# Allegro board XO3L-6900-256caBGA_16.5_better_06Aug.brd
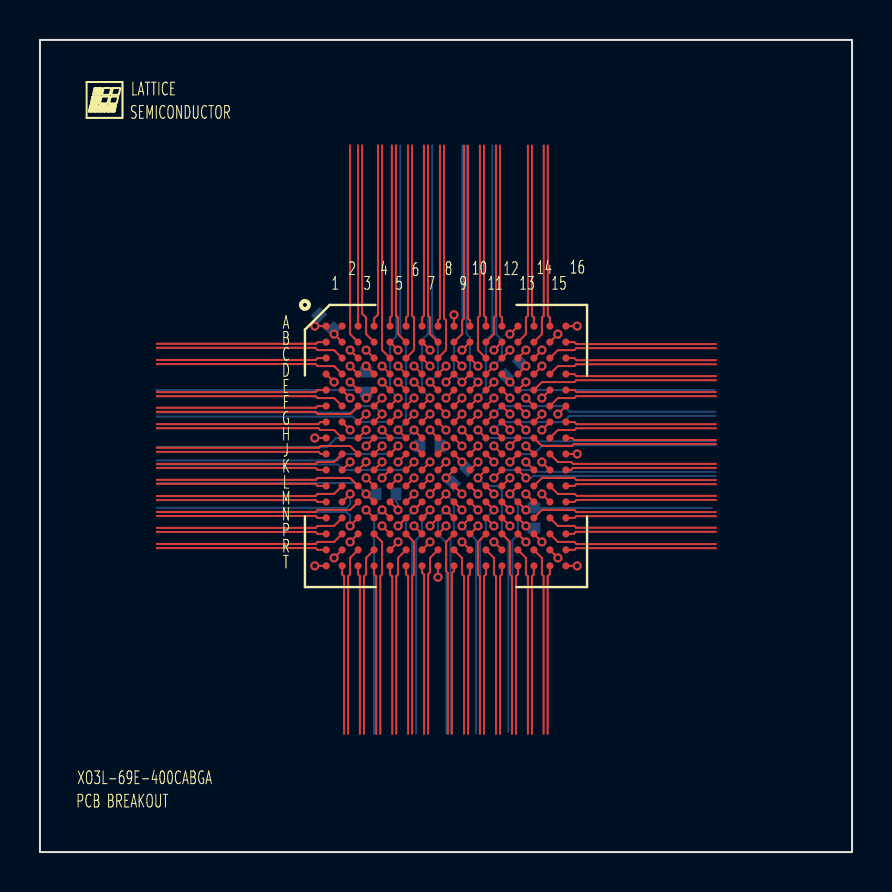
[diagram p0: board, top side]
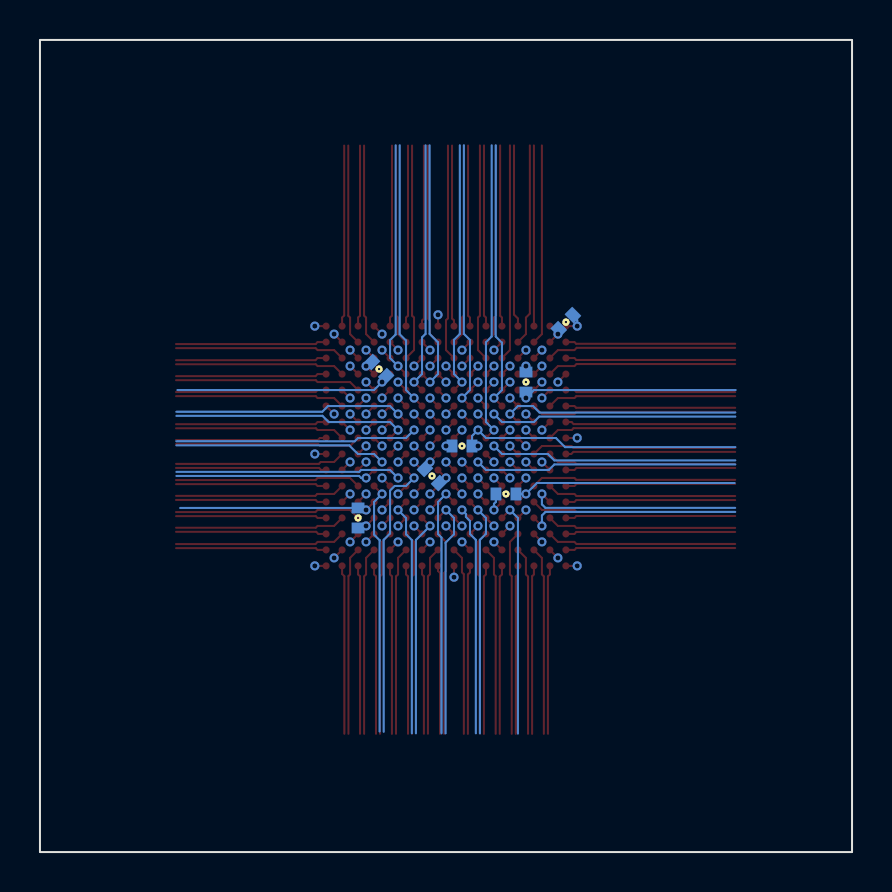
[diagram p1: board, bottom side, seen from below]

Outline 40.64 x 40.64 mm; copper layers: TOP, L2_GND, L3_SIGNAL, L4_SIGNAL, L5_PWR, BOTTOM. Coordinates in mm from the lower left corner of the outline.
Outline path: rectangle 0,0 40.64,40.64

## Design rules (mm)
net group CDPB4: nets PB4C PB4D
net group CDPB13: nets PB13C PB13D
net group CDPB18: nets PB18C PB18D
net group CDPB26: nets PB26C PB26D
net group CDPB31: nets PB31C PB31D
net group CDPB38: nets PB38C PB38D
net group CDPL2: nets PL2C PL2D
net group CDPL4: nets PL4C PL4D
net group CDPL6: nets PL6C PL6D
net group CDPL7: nets PL7C PL7D
net group CDPL9: nets PL9C PL9D
net group CDPL10: nets PL10C PL10D
net group CDPL15: nets PL15C PL15D
net group CDPL16: nets PL16C PL16D
net group CDPL19: nets PL19C PL19D
net group CDPL21: nets PL21C PL21D
net group CDPL23: nets PL23C PL23D
net group CDPL25: nets PL25C PL25D
net group CDPR2: nets PR2C PR2D
net group CDPR4: nets PR4C PR4D
net group CDPR6: nets PR6C PR6D
net group CDPR7: nets PR7C PR7D
net group CDPR10: nets PR10C PR10D
net group CDPR11: nets PR11C PR11D
net group CDPR16: nets PR16C PR16D
net group CDPR17: nets PR17C PR17D
net group CDPR19: nets PR19C PR19D
net group CDPR21: nets PR21C PR21D
net group CDPR23: nets PR23C PR23D
net group CDPR25: nets PR25C PR25D
net group CDPT14: nets PT14C PT14D
net group CDPT17: nets PT17C PT17D
net group CDPT22: nets PT22C PT22D
net group CDPT27: nets PT27C PT27D
net group CDPT36: nets PT36C PT36D
net group PB4: nets PB4A PB4B
net group PB6: nets PB6A PB6B
net group PB7: nets PB7A PB7B
net group PB9: nets PB9A PB9B
net group PB10: nets PB10A PB10B
net group PB12: nets PB12A PB12B
net group PB13: nets PB13A PB13B
net group PB15: nets PB15A PB15B
net group PB16: nets PB16A PB16B
net group PB18: nets PB18A PB18B
net group PB21: nets PB21A PB21B
net group PB23: nets PB23A PB23B
net group PB26: nets PB26A PB26B
net group PB28: nets PB28A PB28B
net group PB29: nets PB29A PB29B
net group PB31: nets PB31A PB31B
net group PB34: nets PB34A PB34B
net group PB35: nets PB35A PB35B
net group PB37: nets PB37A PB37B
net group PB38: nets PB38A PB38B
net group PL3: nets PL3A PL3B
net group PL4: nets PL4A PL4B
net group PL6: nets PL6A PL6B
net group PL8: nets PL8A PL8B
net group PL9: nets PL9A PL9B
net group PL10: nets PL10A PL10B
net group PL11: nets PL11A PL11B
net group PL12: nets PL12A PL12B
net group PL15: nets PL15A PL15B
net group PL17: nets PL17A PL17B
net group PL19: nets PL19A PL19B
net group PL22: nets PL22A PL22B
net group PL24: nets PL24A PL24B
net group PL25: nets PL25A PL25B
net group PR2: nets PR2A PR2B
net group PR3: nets PR3A PR3B
net group PR5: nets PR5A PR5B
net group PR7: nets PR7A PR7B
net group PR9: nets PR9A PR9B
net group PR11: nets PR11A PR11B
net group PR12: nets PR12A PR12B
net group PR15: nets PR15A PR15B
net group PR16: nets PR16A PR16B
net group PR17: nets PR17A PR17B
net group PR18: nets PR18A PR18B
net group PR21: nets PR21A PR21B
net group PR23: nets PR23A PR23B
net group PR24: nets PR24A PR24B
net group PT9: nets PT9A PT9B
net group PT10: nets PT10A PT10B
net group PT11: nets PT11A PT11B
net group PT12: nets PT12A PT12B
net group PT14: nets PT14A PT14B
net group PT15: nets PT15A PT15B
net group PT16: nets PT16A PT16B
net group PT17: nets PT17A PT17B
net group PT18: nets PT18A PT18B
net group PT21: nets PT21A PT21B
net group PT22: nets PT22A PT22B
net group PT25: nets PT25A PT25B
net group PT26: nets PT26A PT26B
net group PT27: nets PT27A PT27B
net group PT28: nets PT28A PT28B
net group PT32: nets PT32A PT32B
net group PT33: nets PT33A PT33B
net group PT34: nets PT34A PT34B
net group PT35: nets PT35A PT35B
net group PT36: nets PT36A PT36B

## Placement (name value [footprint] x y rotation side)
BGA  -  [BGA256C80P16X16_1400X1400X17-1]  20.32 20.32 270 top
C1  VAL  [C0402]  16.32 23.52 90 bottom
C2  VAL  [C0402]  23.67 24.17 45 bottom
C3  VAL  [C0402]  14.32 26.52 315 bottom
C4  VAL  [C0402]  19.52 20.32 0 bottom
C5  VAL  [C0402]  24.72 16.72 270 bottom
C6  VAL  [C0402]  21.02 18.82 45 bottom
C7  VAL  [C0402]  17.32 17.92 0 bottom
NOREF  -  []  24.69 13 0 top

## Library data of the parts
BGA = BGA256C80P16X16_1400X1400X17-1
C1-C7 = C0402: User Part Number: UPN; Tolerance: TOL

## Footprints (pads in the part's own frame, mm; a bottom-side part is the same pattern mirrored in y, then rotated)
BGA256C80P16X16_1400X1400X17-1
  round 0.356 smd: A1(-6,-6) A2(-6,-5.2) A3(-6,-4.4) A4(-6,-3.6) A5(-6,-2.8) A6(-6,-2) A7(-6,-1.2) A8(-6,-0.4) A9(-6,0.4) A10(-6,1.2) A11(-6,2) A12(-6,2.8) A13(-6,3.6) A14(-6,4.4) A15(-6,5.2) A16(-6,6) B1(-5.2,-6) B2(-5.2,-5.2) B3(-5.2,-4.4) B4(-5.2,-3.6) B5(-5.2,-2.8) B6(-5.2,-2) B7(-5.2,-1.2) B8(-5.2,-0.4) B9(-5.2,0.4) B10(-5.2,1.2) B11(-5.2,2) B12(-5.2,2.8) B13(-5.2,3.6) B14(-5.2,4.4) B15(-5.2,5.2) B16(-5.2,6) C1(-4.4,-6) C2(-4.4,-5.2) C3(-4.4,-4.4) C4(-4.4,-3.6) C5(-4.4,-2.8) C6(-4.4,-2) C7(-4.4,-1.2) C8(-4.4,-0.4) C9(-4.4,0.4) C10(-4.4,1.2) C11(-4.4,2) C12(-4.4,2.8) C13(-4.4,3.6) C14(-4.4,4.4) C15(-4.4,5.2) C16(-4.4,6) D1(-3.6,-6) D2(-3.6,-5.2) D3(-3.6,-4.4) D4(-3.6,-3.6) D5(-3.6,-2.8) D6(-3.6,-2) D7(-3.6,-1.2) D8(-3.6,-0.4) D9(-3.6,0.4) D10(-3.6,1.2) D11(-3.6,2) D12(-3.6,2.8) D13(-3.6,3.6) D14(-3.6,4.4) D15(-3.6,5.2) D16(-3.6,6) E1(-2.8,-6) E2(-2.8,-5.2) E3(-2.8,-4.4) E4(-2.8,-3.6) E5(-2.8,-2.8) E6(-2.8,-2) E7(-2.8,-1.2) E8(-2.8,-0.4) E9(-2.8,0.4) E10(-2.8,1.2) E11(-2.8,2) E12(-2.8,2.8) E13(-2.8,3.6) E14(-2.8,4.4) E15(-2.8,5.2) E16(-2.8,6) F1(-2,-6) F2(-2,-5.2) F3(-2,-4.4) F4(-2,-3.6) F5(-2,-2.8) F6(-2,-2) F7(-2,-1.2) F8(-2,-0.4) F9(-2,0.4) F10(-2,1.2) F11(-2,2) F12(-2,2.8) F13(-2,3.6) F14(-2,4.4) F15(-2,5.2) F16(-2,6) G1(-1.2,-6) G2(-1.2,-5.2) G3(-1.2,-4.4) G4(-1.2,-3.6) G5(-1.2,-2.8) G6(-1.2,-2) G7(-1.2,-1.2) G8(-1.2,-0.4) G9(-1.2,0.4) G10(-1.2,1.2) G11(-1.2,2) G12(-1.2,2.8) G13(-1.2,3.6) G14(-1.2,4.4) G15(-1.2,5.2) G16(-1.2,6) H1(-0.4,-6) H2(-0.4,-5.2) H3(-0.4,-4.4) H4(-0.4,-3.6) H5(-0.4,-2.8) H6(-0.4,-2) H7(-0.4,-1.2) H8(-0.4,-0.4) H9(-0.4,0.4) H10(-0.4,1.2) H11(-0.4,2) H12(-0.4,2.8) H13(-0.4,3.6) H14(-0.4,4.4) H15(-0.4,5.2) H16(-0.4,6) J1(0.4,-6) J2(0.4,-5.2) J3(0.4,-4.4) J4(0.4,-3.6) J5(0.4,-2.8) J6(0.4,-2) J7(0.4,-1.2) J8(0.4,-0.4) J9(0.4,0.4) J10(0.4,1.2) J11(0.4,2) J12(0.4,2.8) J13(0.4,3.6) J14(0.4,4.4) J15(0.4,5.2) J16(0.4,6) K1(1.2,-6) K2(1.2,-5.2) K3(1.2,-4.4) K4(1.2,-3.6) K5(1.2,-2.8) K6(1.2,-2) K7(1.2,-1.2) K8(1.2,-0.4) K9(1.2,0.4) K10(1.2,1.2) K11(1.2,2) K12(1.2,2.8) K13(1.2,3.6) K14(1.2,4.4) K15(1.2,5.2) K16(1.2,6) L1(2,-6) L2(2,-5.2) L3(2,-4.4) L4(2,-3.6) L5(2,-2.8) L6(2,-2) L7(2,-1.2) L8(2,-0.4) L9(2,0.4) L10(2,1.2) L11(2,2) L12(2,2.8) L13(2,3.6) L14(2,4.4) L15(2,5.2) L16(2,6) M1(2.8,-6) M2(2.8,-5.2) M3(2.8,-4.4) M4(2.8,-3.6) M5(2.8,-2.8) M6(2.8,-2) M7(2.8,-1.2) M8(2.8,-0.4) M9(2.8,0.4) M10(2.8,1.2) M11(2.8,2) M12(2.8,2.8) M13(2.8,3.6) M14(2.8,4.4) M15(2.8,5.2) M16(2.8,6) N1(3.6,-6) N2(3.6,-5.2) N3(3.6,-4.4) N4(3.6,-3.6) N5(3.6,-2.8) N6(3.6,-2) N7(3.6,-1.2) N8(3.6,-0.4) N9(3.6,0.4) N10(3.6,1.2) N11(3.6,2) N12(3.6,2.8) N13(3.6,3.6) N14(3.6,4.4) N15(3.6,5.2) N16(3.6,6) P1(4.4,-6) P2(4.4,-5.2) P3(4.4,-4.4) P4(4.4,-3.6) P5(4.4,-2.8) P6(4.4,-2) P7(4.4,-1.2) P8(4.4,-0.4) P9(4.4,0.4) P10(4.4,1.2) P11(4.4,2) P12(4.4,2.8) P13(4.4,3.6) P14(4.4,4.4) P15(4.4,5.2) P16(4.4,6) R1(5.2,-6) R2(5.2,-5.2) R3(5.2,-4.4) R4(5.2,-3.6) R5(5.2,-2.8) R6(5.2,-2) R7(5.2,-1.2) R8(5.2,-0.4) R9(5.2,0.4) R10(5.2,1.2) R11(5.2,2) R12(5.2,2.8) R13(5.2,3.6) R14(5.2,4.4) R15(5.2,5.2) R16(5.2,6) T1(6,-6) T2(6,-5.2) T3(6,-4.4) T4(6,-3.6) T5(6,-2.8) T6(6,-2) T7(6,-1.2) T8(6,-0.4) T9(6,0.4) T10(6,1.2) T11(6,2) T12(6,2.8) T13(6,3.6) T14(6,4.4) T15(6,5.2) T16(6,6)
C0402
  rect 0.54x0.64 smd: 1(-0.5,0) 2(0.5,0)

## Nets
GND: BGA.B2 BGA.B15 BGA.C3 BGA.C14 BGA.D4 BGA.D13 BGA.E5 BGA.E12 BGA.F6 BGA.F11 BGA.H8 BGA.H9 BGA.J8 BGA.J9 BGA.L6 BGA.L11 BGA.M5 BGA.M12 BGA.N4 BGA.N13 BGA.P3 BGA.P14 BGA.R2 BGA.R15 C1.2 C2.2 C3.2 C4.2 C5.2 C6.2 C7.2
VCC: BGA.A1 BGA.A16 BGA.G7 BGA.G10 BGA.K7 BGA.K10 BGA.T1 BGA.T16 C3.1
VCCIO0: BGA.D5 BGA.D12 BGA.G8 BGA.G9 C2.1
VCCIO1: BGA.E13 BGA.H10 BGA.J10 BGA.M13 C5.1
VCCIO2: BGA.K8 BGA.K9 BGA.N5 BGA.N12 C6.1
VCCIO3: BGA.M4 C7.1
VCCIO4: BGA.H7 BGA.J7 C4.1
VCCIO5: BGA.E4 C1.1
NC: BGA.A2
PB4A: BGA.P4
PB4B: BGA.T4
PB4C: BGA.T2
PB4D: BGA.R3
PB6A: BGA.R5
PB6B: BGA.P5
PB7A: BGA.T3
PB7B: BGA.R4
PB9A: BGA.T5
PB9B: BGA.R6
PB10A: BGA.N6
PB10B: BGA.L7
PB12A: BGA.P6
PB12B: BGA.T6
PB13A: BGA.R7
PB13B: BGA.P7
PB13C: BGA.M7
PB13D: BGA.N7
PB15A: BGA.M6
PB15B: BGA.L8
PB16A: BGA.T7
PB16B: BGA.R8
PB18A: BGA.P8
PB18B: BGA.T8
PB18C: BGA.N8
PB18D: BGA.L9
PB21A: BGA.M8
PB21B: BGA.N9
PB23A: BGA.T9
PB23B: BGA.P9
PB26A: BGA.R9
PB26B: BGA.T10
PB26C: BGA.M9
PB26D: BGA.L10
PB28A: BGA.N10
PB28B: BGA.M11
PB29A: BGA.P10
PB29B: BGA.R10
PB31A: BGA.T11
PB31B: BGA.P11
PB31C: BGA.M10
PB31D: BGA.N11
PB34A: BGA.R13
PB34B: BGA.T14
PB35A: BGA.R11
PB35B: BGA.T12
PB37A: BGA.P12
PB37B: BGA.T13
PB38A: BGA.R12
PB38B: BGA.P13
PB38C: BGA.T15
PB38D: BGA.R14
PL2C: BGA.B1
PL2D: BGA.C2
PL3A: BGA.D3
PL3B: BGA.D1
PL4A: BGA.E2
PL4B: BGA.E3
PL4C: BGA.C1
PL4D: BGA.D2
PL6A: BGA.E1
PL6B: BGA.F2
PL6C: BGA.F4
PL6D: BGA.G6
PL7C: BGA.G5
PL7D: BGA.G4
PL8A: BGA.F3
PL8B: BGA.F1
PL9A: BGA.G2
PL9B: BGA.G3
PL9C: BGA.F5
PL9D: BGA.H6
PL10A: BGA.G1
PL10B: BGA.H2
PL10C: BGA.H4
PL10D: BGA.J6
PL11A: BGA.H3
PL11B: BGA.H1
PL12A: BGA.J1
PL12B: BGA.J3
PL15A: BGA.J2
PL15B: BGA.K1
PL15C: BGA.H5
PL15D: BGA.J4
PL16C: BGA.J5
PL16D: BGA.K6
PL17A: BGA.K3
PL17B: BGA.K2
PL19A: BGA.L1
PL19B: BGA.L3
PL19C: BGA.K4
PL19D: BGA.L5
PL21C: BGA.K5
PL21D: BGA.L4
PL22A: BGA.L2
PL22B: BGA.M1
PL23C: BGA.N2
PL23D: BGA.P1
PL24A: BGA.M3
PL24B: BGA.N1
PL25A: BGA.M2
PL25B: BGA.N3
PL25C: BGA.R1
PL25D: BGA.P2
PR2A: BGA.D14
PR2B: BGA.E15
PR2C: BGA.C15
PR2D: BGA.B16
PR3A: BGA.D16
PR3B: BGA.E14
PR4C: BGA.C16
PR4D: BGA.D15
PR5A: BGA.E16
PR5B: BGA.F15
PR6C: BGA.F13
PR6D: BGA.G12
PR7A: BGA.F14
PR7B: BGA.F16
PR7C: BGA.F12
PR7D: BGA.G13
PR9A: BGA.G15
PR9B: BGA.G14
PR10C: BGA.G11
PR10D: BGA.H12
PR11A: BGA.G16
PR11B: BGA.H15
PR11C: BGA.H13
PR11D: BGA.J12
PR12A: BGA.H14
PR12B: BGA.H16
PR15A: BGA.J16
PR15B: BGA.J14
PR16A: BGA.J15
PR16B: BGA.K16
PR16C: BGA.H11
PR16D: BGA.J13
PR17A: BGA.K14
PR17B: BGA.K15
PR17C: BGA.J11
PR17D: BGA.L12
PR18A: BGA.L16
PR18B: BGA.L14
PR19C: BGA.K13
PR19D: BGA.K12
PR21A: BGA.L15
PR21B: BGA.M16
PR21C: BGA.K11
PR21D: BGA.L13
PR23A: BGA.M14
PR23B: BGA.M15
PR23C: BGA.N15
PR23D: BGA.P16
PR24A: BGA.N16
PR24B: BGA.N14
PR25C: BGA.P15
PR25D: BGA.R16
PT9A: BGA.C4
PT9B: BGA.B5
PT9C: BGA.B3
PT10A: BGA.A4
PT10B: BGA.C5
PT11A: BGA.A5
PT11B: BGA.B6
PT12A: BGA.A3
PT12B: BGA.B4
PT14A: BGA.D6
PT14B: BGA.E7
PT14C: BGA.C6
PT14D: BGA.A6
PT15A: BGA.B7
PT15B: BGA.C7
PT16A: BGA.E6
PT16B: BGA.D7
PT17A: BGA.F7
PT17B: BGA.E8
PT17C: BGA.A7
PT17D: BGA.B8
PT18A: BGA.C8
PT18B: BGA.A8
PT21A: BGA.D8
PT21B: BGA.E9
PT22A: BGA.F8
PT22B: BGA.D9
PT22C: BGA.A9
PT22D: BGA.C9
PT25A: BGA.B9
PT25B: BGA.A10
PT26A: BGA.F9
PT26B: BGA.E11
PT27A: BGA.D10
PT27B: BGA.E10
PT27C: BGA.C10
PT27D: BGA.B10
PT28A: BGA.A11
PT28B: BGA.C11
PT32A: BGA.F10
PT32B: BGA.D11
PT33A: BGA.B11
PT33B: BGA.A12
PT34A: BGA.B13
PT34B: BGA.A14
PT35A: BGA.C12
PT35B: BGA.B12
PT36A: BGA.B14
PT36B: BGA.A15
PT36C: BGA.A13
PT36D: BGA.C13

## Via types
v1: diameter 0.457, hole 0.254, TOP to BOTTOM, 158 vias

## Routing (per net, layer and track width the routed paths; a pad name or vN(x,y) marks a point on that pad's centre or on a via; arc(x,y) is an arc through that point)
GND: length 16.6
  TOP w0.102: v1(24.32,24.32) BGA.D13 ; v1(15.52,15.52) BGA.P3 ; v1(21.12,19.52) BGA.J9 ; v1(20.32,20.32) BGA.J8 ; v1(18.72,22.72) BGA.F6 ; v1(25.92,25.92) BGA.B15 ; v1(14.72,25.92) BGA.B2 ; v1(22.72,22.72) BGA.F11 ; v1(18.72,18.72) BGA.L6 ; v1(21.12,20.32) BGA.H9 ; v1(23.52,17.12) BGA.M12 ; v1(23.52,22.72) BGA.E12 ; v1(22.72,17.92) BGA.L11 ; v1(16.32,24.32) BGA.D4 ; v1(25.92,14.72) BGA.R15 ; v1(15.52,25.12) BGA.C3 ; v1(16.32,17.12) BGA.N4 ; v1(25.12,15.52) BGA.P14 ; BGA.M5 v1(17.92,17.12) ; v1(17.12,23.52) BGA.E5 ; v1(25.12,25.12) BGA.C14 ; v1(24.32,16.32) BGA.N13 ; v1(19.52,21.12) BGA.H8 ; v1(14.72,14.72) BGA.R2
  BOTTOM w0.102: C1.2 v1(16.32,24.32) ; C2.2 24.12,24.52 v1(24.32,24.32) ; v1(24.32,16.32) 24.62,16.32 C5.2 ; C4.2 v1(20.32,20.32) ; C7.2 17.82,17.52 17.92,17.43 v1(17.92,17.12) ; C6.2 21.37,19.27 v1(21.12,19.52) ; C3.2 14.72,26.12 v1(14.72,25.92)
VCC: length 5.2
  TOP w0.102: v1(26.89,26.32) BGA.A16 ; v1(13.75,26.32) BGA.A1 ; v1(19.52,21.92) BGA.G7 ; v1(26.89,14.32) BGA.T16 ; v1(21.92,21.92) BGA.G10 ; v1(13.75,14.32) BGA.T1 ; v1(21.92,19.52) BGA.K10 ; v1(19.52,19.52) BGA.K7
  BOTTOM w0.102: C3.1 13.97,26.84 13.75,26.62 v1(13.75,26.32)
VCCIO0: length 22.8
  TOP w0.102: v1(23.52,23.52) BGA.D12 ; v1(21.12,21.92) BGA.G9 ; v1(20.32,21.12) BGA.G8 ; v1(17.12,24.32) BGA.D5
  L3_SIGNAL w0.102: v1(17.12,24.32) BGA.D5 17.52,23.32 17.56,23.32 17.75,23.12 18.09,23.12 18.32,22.89 18.32,22.55 18.55,22.32 18.89,22.32 19.12,22.09 19.12,21.75 19.35,21.52 BGA.G8 v1(20.32,21.12) v1(21.12,21.92) 21.52,22.32 22.89,22.32 23.12,22.55 23.12,23.12 v1(23.52,23.52)
  BOTTOM w0.102: C2.1 23.32,23.72 v1(23.52,23.52) 23.92,23.12 24.49,23.12 33.76,23.12
VCCIO1: length 22.2
  TOP w0.102: v1(24.32,23.52) BGA.E13 ; v1(21.92,20.32) BGA.J10 ; v1(24.32,17.12) BGA.M13 ; v1(21.12,21.12) BGA.H10
  L3_SIGNAL w0.102: v1(24.32,23.52) BGA.E13 23.92,22.49 23.75,22.32 23.35,22.32 23.12,22.09 23.12,21.75 22.89,21.52 21.52,21.52 v1(21.12,21.12) v1(21.92,20.32) 22.32,19.92 22.32,19.12 22.32,18.55 22.55,18.32 22.89,18.32 23.12,18.09 23.12,17.75 23.35,17.52 BGA.M13 v1(24.32,17.12)
  BOTTOM w0.102: 33.62,17.22 C5.1 24.72,17.18 24.66,17.12 v1(24.32,17.12)
VCCIO2: length 26
  TOP w0.102: v1(20.32,19.52) BGA.K8 ; v1(23.52,16.32) BGA.N12 ; v1(17.12,17.12) BGA.N5 ; BGA.K9 v1(20.32,18.72)
  L3_SIGNAL w0.102: v1(23.52,16.32) BGA.N12 22.55,16.72 22.32,16.95 22.32,17.29 22.09,17.52 21.75,17.52 21.52,17.75 21.52,19.69 21.29,19.92 20.72,19.92 v1(20.32,19.52) v1(20.32,18.72) 19.92,18.32 19.92,16.95 19.69,16.72 19.35,16.72 BGA.N5 v1(17.12,17.12)
  BOTTOM w0.102: C6.1 20.57,18.47 v1(20.32,18.72) ; 16.72,5.93 16.72,16.72 v1(17.12,17.12)
VCCIO3: length 11.7
  TOP w0.102: BGA.M4 v1(16.32,17.92)
  BOTTOM w0.102: C7.1 v1(16.32,17.92) 15.77,18.47 5.87,18.47
VCCIO4: length 15.6
  TOP w0.102: v1(18.72,20.32) BGA.J7 ; v1(18.72,21.12) BGA.H7
  BOTTOM w0.102: v1(18.72,20.32) C4.1 19.02,20.82 v1(18.72,21.12) 18.32,20.72 14.82,20.72 14.36,20.26 5.84,20.26
VCCIO5: length 11.5
  TOP w0.102: v1(16.32,22.72) BGA.E4
  BOTTOM w0.102: 5.83,23.12 15.92,23.12 v1(16.32,22.72) C1.1
PB4A: length 10.2
  TOP w0.102: 17.03,5.92 17.03,13.8 17.12,13.89 17.12,15.52 BGA.P4
PB4B: length 8.4
  TOP w0.102: 16.83,5.92 16.83,13.79 16.72,13.89 BGA.T4
PB4C: length 8.4
  TOP w0.102: 15.22,5.92 15.22,13.79 15.12,13.89 BGA.T2
PB4D: length 9.4
  TOP w0.102: 15.42,5.92 15.42,13.8 15.52,13.89 15.52,14.72 BGA.R3
PB6A: length 11
  TOP w0.102: v1(17.92,15.52) BGA.R5
  L3_SIGNAL w0.102: 17.23,5.96 17.23,15.49 17.45,15.7 17.52,15.78 17.66,15.78 v1(17.92,15.52)
PB6B: length 11.2
  TOP w0.102: v1(17.12,16.32) BGA.P5
  L3_SIGNAL w0.102: 17.03,5.96 17.03,15.57 17.3,15.85 17.38,15.92 17.38,16.06 v1(17.12,16.32)
PB7A: length 8.4
  TOP w0.102: BGA.T3 15.92,13.89 16.01,13.8 16.01,5.92
PB7B: length 9.4
  TOP w0.102: BGA.R4 16.32,14.72 16.32,13.89 16.21,13.79 16.21,5.92
PB9A: length 8.4
  TOP w0.102: BGA.T5 17.52,13.89 17.63,13.78 17.63,5.92
PB9B: length 9.4
  TOP w0.102: BGA.R6 17.92,14.72 17.92,13.89 17.83,13.81 17.83,5.92
PB10A: length 11.8
  TOP w0.102: v1(17.92,16.32) BGA.N6 v1(17.92,16.32)
  L4_SIGNAL w0.102: 17.86,5.97 17.86,14.94 17.52,15.28 17.52,15.92 v1(17.92,16.32)
PB10B: length 14.1
  TOP w0.102: v1(19.52,18.72) BGA.L7
  L4_SIGNAL w0.102: 18.06,5.97 18.06,14.94 18.32,15.2 18.32,17.29 18.55,17.52 18.59,17.52 18.94,17.52 19.12,17.7 BGA.L7 v1(19.52,18.72)
PB12A: length 10.2
  TOP w0.102: BGA.P6 18.72,15.52 18.72,13.89 18.63,13.8 18.63,5.92
PB12B: length 8.4
  TOP w0.102: BGA.T6 18.32,13.89 18.42,13.79 18.42,5.92
PB13A: length 11
  TOP w0.102: v1(19.52,15.52) BGA.R7
  L3_SIGNAL w0.102: 18.76,5.95 18.76,15.42 19.12,15.78 19.26,15.78 v1(19.52,15.52)
PB13B: length 11.2
  TOP w0.102: v1(18.72,16.32) BGA.P7
  L3_SIGNAL w0.102: v1(18.72,16.32) 18.98,16.06 18.98,15.92 18.56,15.5 18.56,5.95
PB13C: length 12.6
  TOP w0.102: v1(18.72,17.12) BGA.M7 v1(18.72,17.12)
  BOTTOM w0.102: 18.62,5.94 18.62,15.62 18.32,15.93 18.32,16.72 v1(18.72,17.12)
PB13D: length 12
  TOP w0.102: v1(19.52,17.12) BGA.N7
  BOTTOM w0.102: v1(19.52,17.12) 19.32,16.92 19.32,16.77 19.12,16.57 19.12,15.92 18.83,15.62 18.83,5.94
PB15A: length 14.3
  TOP w0.102: v1(18.72,17.92) BGA.M6 v1(18.72,17.92)
  L3_SIGNAL w0.102: 5.85,17.8 14.97,17.8 15.25,17.52 16.7,17.52 17.1,17.92 v1(18.72,17.92)
PB15B: length 15.3
  TOP w0.102: v1(19.52,17.92) BGA.L8 v1(19.52,17.92)
  L3_SIGNAL w0.102: v1(19.52,17.92) 19.12,18.32 18.36,18.32 18.16,18.12 16.89,18.12 16.69,18.32 15.26,18.32 14.95,18.01 5.85,18.01
PB16A: length 8.4
  TOP w0.102: BGA.T7 19.12,13.99 19.22,13.89 19.22,5.92
PB16B: length 9.4
  TOP w0.102: 19.43,5.92 19.43,13.9 19.52,14 19.52,14.72 BGA.R8
PB18A: length 11.4
  TOP w0.102: v1(20.32,16.32) BGA.P8
  L3_SIGNAL w0.102: v1(20.32,16.32) 20.15,15.24 20.24,15.12 20.34,15.11 20.42,15.11 21.11,14.42 21.11,5.97
PB18B: length 11.1
  TOP w0.102: v1(19.92,13.75) BGA.T8
  L3_SIGNAL w0.102: v1(19.92,13.75) 20.09,14.84 20.2,14.92 20.34,14.9 20.9,14.34 20.9,5.97
PB18C: length 11.2
  TOP w0.102: v1(19.52,16.32) BGA.N8
  L4_SIGNAL w0.102: 19.27,5.96 19.27,14.7 19.03,14.94 19.03,15.83 v1(19.52,16.32)
PB18D: length 13.5
  TOP w0.102: v1(21.12,17.92) BGA.L9
  L4_SIGNAL w0.102: v1(21.12,17.92) 20.72,17.52 20.15,17.52 19.92,17.29 19.92,15.15 19.47,14.71 19.47,5.96
PB21A: length 12.8
  TOP w0.102: v1(20.32,17.92) BGA.M8
  BOTTOM w0.102: 20.55,5.94 20.55,15.74 20.72,15.91 20.72,17.52 v1(20.32,17.92)
PB21B: length 12.1
  TOP w0.102: v1(20.32,17.12) BGA.N9
  BOTTOM w0.102: 20.34,5.94 20.34,15.48 19.92,15.9 19.92,16.72 v1(20.32,17.12)
PB23A: length 8.4
  TOP w0.102: 20.62,5.92 20.62,13.96 20.72,14.07 BGA.T9
PB23B: length 10.2
  TOP w0.102: BGA.P9 20.32,15.52 20.32,14.05 20.41,13.96 20.41,5.92
PB26A: length 9.4
  TOP w0.102: BGA.R9 21.12,14.72 21.12,13.9 21.22,13.8 21.22,5.92
PB26B: length 8.4
  TOP w0.102: BGA.T10 21.52,13.89 21.43,13.8 21.43,5.92
PB26C: length 12
  TOP w0.102: v1(21.12,17.12) BGA.M9
  L4_SIGNAL w0.102: v1(21.12,17.12) 20.72,16.72 20.72,15.11 21.01,14.82 21.01,5.95
PB26D: length 12.8
  TOP w0.102: v1(21.92,17.92) BGA.L10
  L4_SIGNAL w0.102: v1(21.92,17.92) 21.52,17.52 21.52,15.13 21.21,14.82 21.21,5.95
PB28A: length 11.2
  TOP w0.102: v1(21.12,16.32) BGA.N10
  BOTTOM w0.102: v1(21.12,16.32) 21.83,15.61 21.83,5.94
PB28B: length 12
  TOP w0.102: v1(22.72,17.12) BGA.M11
  BOTTOM w0.102: v1(22.72,17.12) 22.32,16.72 22.32,15.91 22.03,15.61 22.03,5.94
PB29A: length 11.1
  TOP w0.102: v1(21.92,16.32) BGA.P10
  L3_SIGNAL w0.102: 21.98,5.95 21.98,15.59 21.72,15.85 21.72,16.12 v1(21.92,16.32)
PB29B: length 11
  TOP w0.102: v1(21.12,15.52) BGA.R10
  L3_SIGNAL w0.102: 21.78,5.95 21.78,15.5 21.56,15.72 21.32,15.72 v1(21.12,15.52)
PB31A: length 8.4
  TOP w0.102: 22.22,5.92 22.22,13.79 22.32,13.89 BGA.T11
PB31B: length 10.2
  TOP w0.102: BGA.P11 21.92,15.52 21.92,13.89 22.02,13.8 22.02,5.92
PB31C: length 12
  TOP w0.102: v1(21.92,17.12) BGA.M10
  L4_SIGNAL w0.102: v1(21.92,17.12) 22.32,16.72 22.32,15.15 22.63,14.85 22.63,5.96
PB31D: length 11.2
  TOP w0.102: v1(22.72,16.32) BGA.N11
  L4_SIGNAL w0.102: v1(22.72,16.32) 23.13,15.91 23.13,15.14 22.83,14.85 22.83,5.96
PB34A: length 9.4
  TOP w0.102: 24.42,5.92 24.42,13.8 24.32,13.89 24.32,14.72 BGA.R13
PB34B: length 8.4
  TOP w0.102: 24.62,5.92 24.62,13.8 24.72,13.89 BGA.T14
PB35A: length 9.4
  TOP w0.102: BGA.R11 22.72,14.72 22.72,13.89 22.82,13.79 22.82,5.92
PB35B: length 8.4
  TOP w0.102: BGA.T12 23.12,13.89 23.03,13.8 23.03,5.92
PB37A: length 10.2
  TOP w0.102: 23.62,5.92 23.62,13.79 23.52,13.89 23.52,15.52 BGA.P12
PB37B: length 8.4
  TOP w0.102: 23.82,5.92 23.82,13.8 23.92,13.89 BGA.T13
PB38A: length 10.7
  TOP w0.102: v1(22.72,15.52) BGA.R12
  L3_SIGNAL w0.102: 23.43,5.95 23.43,15.33 23.24,15.52 v1(22.72,15.52)
PB38B: length 10.7
  TOP w0.102: v1(24.32,15.52) BGA.P13
  L3_SIGNAL w0.102: v1(24.32,15.52) 23.8,15.52 23.64,15.36 23.64,5.95
PB38C: length 8.4
  TOP w0.102: 25.41,5.92 25.41,13.8 25.52,13.92 BGA.T15
PB38D: length 9.4
  TOP w0.102: BGA.R14 25.12,14.72 25.12,13.89 25.2,13.81 25.2,5.92
PL2C: length 8.5
  TOP w0.102: BGA.B1 13.89,25.52 13.81,25.44 5.85,25.44
PL2D: length 9.5
  TOP w0.102: BGA.C2 14.72,25.12 13.89,25.12 13.78,25.23 5.85,25.23
PL3A: length 10.5
  TOP w0.102: v1(15.52,24.32) BGA.D3
  L4_SIGNAL w0.102: v1(15.52,24.32) 15.26,24.06 15.12,24.06 14.77,24.41 5.81,24.41
PL3B: length 10.4
  TOP w0.102: v1(14.72,23.52) BGA.D1
  L4_SIGNAL w0.102: v1(14.72,23.52) 14.98,23.78 14.98,23.92 14.69,24.21 5.81,24.21
PL4A: length 10.4
  TOP w0.102: v1(15.52,22.72) BGA.E2
  L3_SIGNAL w0.102: v1(15.52,22.72) 15.22,23.02 15.12,23.02 15,22.9 5.85,22.9
PL4B: length 10.4
  TOP w0.102: v1(15.52,23.52) BGA.E3
  L3_SIGNAL w0.102: 5.85,23.11 14.92,23.11 15.04,23.22 15.22,23.22 v1(15.52,23.52)
PL4C: length 8.5
  TOP w0.102: BGA.C1 13.89,24.72 13.8,24.63 5.85,24.63
PL4D: length 9.5
  TOP w0.102: BGA.D2 14.72,24.32 13.89,24.32 13.79,24.42 5.85,24.42
PL6A: length 8.5
  TOP w0.102: 5.85,23.02 13.79,23.02 13.89,23.12 BGA.E1
PL6B: length 9.5
  TOP w0.102: 5.85,22.81 13.8,22.81 13.89,22.72 14.72,22.72 BGA.F2
PL6C: length 12.1
  TOP w0.102: v1(17.12,22.72) BGA.F4
  L4_SIGNAL w0.102: 5.85,22.83 14.83,22.83 15.12,23.12 16.72,23.12 v1(17.12,22.72)
PL6D: length 13.7
  TOP w0.102: v1(18.72,21.92) BGA.G6
  L4_SIGNAL w0.102: v1(18.72,21.92) 18.32,22.32 15.13,22.32 14.83,22.62 5.85,22.62
PL7C: length 12.9
  TOP w0.102: v1(17.92,21.92) BGA.G5
  BOTTOM w0.102: v1(17.92,21.92) BGA.G5 15.92,21.52 15.65,21.79 5.84,21.79
PL7D: length 12.1
  TOP w0.102: v1(17.12,21.92) BGA.G4
  BOTTOM w0.102: v1(17.12,21.92) 16.72,22.32 15.96,22.32 15.64,22 5.84,22
PL8A: length 10.3
  TOP w0.102: 5.85,22.03 13.78,22.03 13.89,21.92 15.52,21.92 BGA.F3
PL8B: length 8.5
  TOP w0.102: 5.85,22.23 13.81,22.23 13.89,22.32 BGA.F1
PL9A: length 11.3
  TOP w0.102: v1(15.52,21.12) BGA.G2
  L3_SIGNAL w0.102: 5.85,22.3 15,22.3 15.72,21.57 15.72,21.32 v1(15.52,21.12)
PL9B: length 11.4
  TOP w0.102: v1(16.32,21.92) BGA.G3
  L3_SIGNAL w0.102: 5.85,22.5 15.08,22.5 15.87,21.72 16.12,21.72 v1(16.32,21.92)
PL9C: length 13.5
  TOP w0.102: v1(17.92,22.72) BGA.F5
  BOTTOM w0.102: 17.83,35.37 17.83,25.8 17.52,25.49 17.52,23.12 v1(17.92,22.72)
PL9D: length 15.1
  TOP w0.102: v1(17.92,21.12) BGA.H6
  BOTTOM w0.102: 18.03,35.37 18.03,25.8 18.32,25.51 18.32,21.52 v1(17.92,21.12)
PL10A: length 8.5
  TOP w0.102: BGA.G1 14.04,21.52 13.93,21.42 5.85,21.42
PL10B: length 9.5
  TOP w0.102: BGA.H2 14.72,21.12 14.03,21.12 13.94,21.21 5.85,21.21
PL10C: length 11.1
  TOP w0.102: v1(16.32,20.32) BGA.H4
  L4_SIGNAL w0.102: 5.85,20.12 15.7,20.12 15.89,20.32 v1(16.32,20.32)
PL10D: length 12.8
  TOP w0.102: v1(17.92,19.52) BGA.J6
  L4_SIGNAL w0.102: 5.85,19.92 17.52,19.92 v1(17.92,19.52)
PL11A: length 11.9
  TOP w0.102: v1(16.32,21.12) BGA.H3
  L3_SIGNAL w0.102: v1(16.32,21.12) 15.9,20.7 15.07,20.7 14.54,21.23 14.54,21.53 14.21,21.86 5.85,21.86
PL11B: length 10.2
  TOP w0.102: v1(13.75,20.72) BGA.H1
  L3_SIGNAL w0.102: v1(13.75,20.72) 13.83,20.72 14.34,21.23 14.34,21.45 14.12,21.66 5.85,21.66
PL12A: length 8.5
  TOP w0.102: BGA.J1 14.05,19.92 13.95,20.03 5.85,20.03
PL12B: length 10.3
  TOP w0.102: 5.85,20.23 13.95,20.23 14.04,20.32 15.52,20.32 BGA.J3
PL15A: length 9.5
  TOP w0.102: 5.85,19.42 13.8,19.42 13.89,19.52 14.72,19.52 BGA.J2
PL15B: length 8.5
  TOP w0.102: BGA.K1 13.89,19.12 13.79,19.22 5.85,19.22
PL15C: length 12.1
  TOP w0.102: v1(17.12,21.12) BGA.H5
  L4_SIGNAL w0.102: 5.85,21.36 14.81,21.36 14.97,21.52 16.72,21.52 v1(17.12,21.12)
PL15D: length 12.2
  TOP w0.102: v1(17.12,20.32) BGA.J4
  L4_SIGNAL w0.102: 5.85,21.15 14.82,21.15 15.25,20.72 16.72,20.72 v1(17.12,20.32)
PL16C: length 12.9
  TOP w0.102: v1(17.92,20.32) BGA.J5
  BOTTOM w0.102: v1(17.92,20.32) BGA.J5 15.22,19.92 14.9,19.6 5.84,19.6
PL16D: length 13.7
  TOP w0.102: v1(18.72,19.52) BGA.K6
  BOTTOM w0.102: 5.84,19.4 14.9,19.4 15.18,19.12 16.95,19.12 BGA.K6 v1(18.72,19.52)
PL17A: length 11.2
  TOP w0.102: v1(16.32,19.52) BGA.K3
  L3_SIGNAL w0.102: 5.85,20.02 15.82,20.02 v1(16.32,19.52)
PL17B: length 10.4
  TOP w0.102: v1(15.52,19.52) BGA.K2
  L3_SIGNAL w0.102: v1(15.52,19.52) 15.16,19.52 14.86,19.82 5.85,19.82
PL19A: length 8.5
  TOP w0.102: BGA.L1 13.89,18.32 13.79,18.42 5.85,18.42
PL19B: length 10.3
  TOP w0.102: 5.85,18.63 13.8,18.63 13.89,18.72 15.52,18.72 BGA.L3
PL19C: length 12.1
  TOP w0.102: v1(17.12,19.52) BGA.K4
  L4_SIGNAL w0.102: v1(17.12,19.52) BGA.K4 15.98,19.12 15.66,18.8 5.85,18.8
PL19D: length 12.9
  TOP w0.102: v1(17.92,18.72) BGA.L5
  L4_SIGNAL w0.102: 5.85,18.6 15.67,18.6 15.95,18.32 BGA.L5 v1(17.92,18.72)
PL21C: length 12
  TOP w0.102: v1(17.12,18.72) BGA.K5
  L3_SIGNAL w0.102: 5.86,19.02 15.85,19.02 15.94,19.12 16.72,19.12 v1(17.12,18.72)
PL21D: length 11.1
  TOP w0.102: v1(16.32,18.72) BGA.L4
  L3_SIGNAL w0.102: v1(16.32,18.72) 15.94,18.72 15.85,18.82 5.86,18.82
PL22A: length 9.5
  TOP w0.102: 5.85,17.82 13.79,17.82 13.89,17.92 14.72,17.92 BGA.L2
PL22B: length 8.5
  TOP w0.102: BGA.M1 13.89,17.52 13.8,17.61 5.85,17.61
PL23C: length 9.5
  TOP w0.102: BGA.N2 14.72,16.32 13.89,16.32 13.8,16.22 5.85,16.22
PL23D: length 8.5
  TOP w0.102: 5.85,16.02 13.8,16.02 13.89,15.92 BGA.P1
PL24A: length 10.3
  TOP w0.102: BGA.M3 15.52,17.12 13.89,17.12 13.79,17.02 5.85,17.02
PL24B: length 8.5
  TOP w0.102: 5.85,16.82 13.8,16.82 13.89,16.72 BGA.N1
PL25A: length 10.8
  TOP w0.102: v1(15.52,17.92) BGA.M2
  BOTTOM w0.102: 5.85,17.22 15.35,17.22 15.52,17.4 v1(15.52,17.92)
PL25B: length 10.8
  TOP w0.102: v1(15.52,16.32) BGA.N3
  BOTTOM w0.102: v1(15.52,16.32) 15.52,16.84 15.34,17.02 5.85,17.02
PL25C: length 8.5
  TOP w0.102: 5.85,15.21 13.8,15.21 13.89,15.12 BGA.R1
PL25D: length 9.5
  TOP w0.102: 5.85,15.42 13.79,15.42 13.89,15.52 14.72,15.52 BGA.P2
PR2A: length 9.9
  TOP w0.102: v1(25.12,24.32) BGA.D14
  L3_SIGNAL w0.102: 33.83,23.62 25.3,23.62 25.12,23.8 v1(25.12,24.32)
PR2B: length 9.9
  TOP w0.102: v1(25.12,22.72) BGA.E15
  L3_SIGNAL w0.102: v1(25.12,22.72) 25.12,23.24 25.29,23.42 33.83,23.42
PR2C: length 8.5
  TOP w0.102: BGA.C15 25.92,25.12 26.75,25.12 26.84,25.22 33.83,25.22
PR2D: length 7.5
  TOP w0.102: BGA.B16 26.75,25.52 26.85,25.42 33.83,25.42
PR3A: length 7.6
  TOP w0.102: 33.83,23.82 26.85,23.82 26.75,23.92 BGA.D16
PR3B: length 9.3
  TOP w0.102: 33.83,23.61 26.84,23.61 26.75,23.52 25.12,23.52 BGA.E14
PR4C: length 7.6
  TOP w0.102: 33.83,24.61 26.85,24.61 26.75,24.72 BGA.C16
PR4D: length 8.5
  TOP w0.102: BGA.D15 25.92,24.32 26.75,24.32 26.84,24.41 33.83,24.41
PR5A: length 7.6
  TOP w0.102: 33.83,23.02 26.85,23.02 26.75,23.12 BGA.E16
PR5B: length 8.5
  TOP w0.102: 33.83,22.82 26.84,22.82 26.75,22.72 25.92,22.72 BGA.F15
PR6C: length 10.4
  TOP w0.102: v1(24.32,21.92) BGA.F13
  L4_SIGNAL w0.102: v1(24.32,21.92) 24.72,22.32 25.5,22.32 25.79,22.61 33.82,22.61
PR6D: length 13.5
  TOP w0.102: v1(23.52,21.12) BGA.G12
  L4_SIGNAL w0.102: 33.82,22.81 25.81,22.81 25.5,23.12 23.27,23.12 23.12,22.97 23.12,21.87 BGA.G12 v1(23.52,21.12)
PR7A: length 10.2
  TOP w0.102: v1(24.32,22.72) BGA.F14
  L3_SIGNAL w0.102: v1(24.32,22.72) BGA.F14 33.81,22.32
PR7B: length 8.5
  TOP w0.102: v1(25.92,21.92) BGA.F16
  L3_SIGNAL w0.102: v1(25.92,21.92) 26.3,21.92 26.5,22.12 33.81,22.12
PR7C: length 11.2
  TOP w0.102: v1(23.52,21.92) BGA.F12
  L4_SIGNAL w0.102: v1(23.52,21.92) 23.92,21.52 25.48,21.52 25.82,21.18 33.82,21.18
PR7D: length 10.3
  TOP w0.102: v1(24.32,21.12) BGA.G13
  L4_SIGNAL w0.102: 33.82,20.98 25.79,20.98 25.54,20.72 24.95,20.72 24.55,21.12 v1(24.32,21.12)
PR9A: length 9.4
  TOP w0.102: v1(25.12,21.12) BGA.G15
  L3_SIGNAL w0.102: v1(25.12,21.12) 25.42,21.42 25.52,21.42 25.64,21.3 33.81,21.3
PR9B: length 9.4
  TOP w0.102: v1(25.12,21.92) BGA.G14
  L3_SIGNAL w0.102: v1(25.12,21.92) 25.42,21.62 25.61,21.62 25.72,21.5 33.81,21.5
PR10C: length 11.9
  TOP w0.102: v1(22.72,21.92) BGA.G11
  BOTTOM w0.102: 33.81,22.03 26.51,22.03 26.22,22.32 26.02,22.32 23.12,22.32 v1(22.72,21.92)
PR10D: length 12
  TOP w0.102: v1(22.72,21.12) BGA.H12
  BOTTOM w0.102: v1(22.72,21.12) 23.12,21.52 26.19,21.52 26.5,21.83 33.81,21.83
PR11A: length 7.6
  TOP w0.102: BGA.G16 26.75,21.52 26.86,21.41 33.83,21.41
PR11B: length 8.5
  TOP w0.102: 33.83,21.21 26.83,21.21 26.75,21.12 25.92,21.12 BGA.H15
PR11C: length 11.6
  TOP w0.102: v1(23.52,20.32) BGA.H13
  L4_SIGNAL w0.102: 33.82,19.4 26.36,19.4 25.64,20.12 25.14,20.12 24.54,20.72 BGA.H13 v1(23.52,20.32)
PR11D: length 12.1
  TOP w0.102: v1(22.72,20.32) BGA.J12
  L4_SIGNAL w0.102: v1(22.72,20.32) BGA.J12 24.76,19.92 25.55,19.92 26.27,19.2 33.82,19.2
PR12A: length 9.3
  TOP w0.102: BGA.H14 25.12,20.32 26.62,20.32 26.72,20.42 33.83,20.42
PR12B: length 7.6
  TOP w0.102: BGA.H16 26.63,20.72 26.73,20.62 33.83,20.62
PR15A: length 10.1
  TOP w0.102: v1(26.89,19.92) BGA.J16
  L3_SIGNAL w0.102: 33.81,20.62 26.02,20.62 25.74,20.34 25.72,20.2 25.8,20.09 v1(26.89,19.92)
PR15B: length 10.4
  TOP w0.102: v1(24.32,20.32) BGA.J14
  L3_SIGNAL w0.102: 33.81,20.83 25.94,20.83 25.53,20.42 25.53,20.34 25.52,20.24 25.4,20.15 v1(24.32,20.32)
PR16A: length 8.5
  TOP w0.102: 33.83,19.42 26.68,19.42 26.59,19.52 25.92,19.52 BGA.J15
PR16B: length 7.6
  TOP w0.102: 33.83,19.22 26.67,19.22 26.57,19.12 BGA.K16
PR16C: length 12.7
  TOP w0.102: v1(21.92,21.12) BGA.H11
  BOTTOM w0.102: v1(21.92,21.12) BGA.H11 24.72,20.72 24.89,20.56 33.81,20.56
PR16D: length 11.2
  TOP w0.102: v1(23.52,19.52) BGA.J13
  BOTTOM w0.102: 33.81,20.35 25.16,20.35 24.73,19.92 BGA.J13 v1(23.52,19.52)
PR17A: length 10.3
  TOP w0.102: v1(24.32,19.52) BGA.K14
  L3_SIGNAL w0.102: 33.83,19.09 24.75,19.09 v1(24.32,19.52)
PR17B: length 9.4
  TOP w0.102: v1(25.12,19.52) BGA.K15
  L3_SIGNAL w0.102: v1(25.12,19.52) 25.45,19.52 25.67,19.3 33.83,19.3
PR17C: length 11.9
  TOP w0.102: v1(22.72,19.52) BGA.J11
  L4_SIGNAL w0.102: v1(22.72,19.52) 23.12,19.12 24.71,19.12 25,18.83 33.82,18.83
PR17D: length 11.2
  TOP w0.102: v1(23.52,18.72) BGA.L12
  L4_SIGNAL w0.102: v1(23.52,18.72) 23.92,18.32 24.66,18.32 24.97,18.63 33.82,18.63
PR18A: length 7.5
  TOP w0.102: BGA.L16 26.75,18.32 26.84,18.41 33.83,18.41
PR18B: length 9.3
  TOP w0.102: BGA.L14 25.12,18.72 26.75,18.72 26.85,18.62 33.83,18.62
PR19C: length 10.1
  TOP w0.102: v1(24.32,18.72) BGA.K13
  BOTTOM w0.102: v1(24.32,18.72) 24.57,18.72 24.67,18.82 33.81,18.82
PR19D: length 11.9
  TOP w0.102: v1(22.72,18.72) BGA.K12
  BOTTOM w0.102: v1(22.72,18.72) BGA.K12 24.15,19.12 24.57,19.12 24.66,19.03 33.81,19.03
PR21A: length 8.5
  TOP w0.102: 33.83,17.82 26.86,17.82 26.77,17.92 25.92,17.92 BGA.L15
PR21B: length 7.6
  TOP w0.102: 33.83,17.62 26.85,17.62 26.75,17.52 BGA.M16
PR21C: length 14.2
  TOP w0.102: v1(21.92,18.72) BGA.K11
  BOTTOM w0.102: 23.44,6.02 23.44,15.63 23.12,15.94 23.12,18.09 22.89,18.32 22.79,18.32 22.32,18.32 v1(21.92,18.72)
PR21D: length 12.7
  TOP w0.102: v1(23.52,17.92) BGA.L13
  BOTTOM w0.102: 23.64,6.03 23.64,15.6 23.92,15.88 23.92,17.29 23.92,17.52 v1(23.52,17.92)
PR23A: length 10.3
  TOP w0.102: v1(24.32,17.92) BGA.M14
  L3_SIGNAL w0.102: v1(24.32,17.92) 24.79,18.39 33.83,18.39
PR23B: length 9.4
  TOP w0.102: v1(25.12,17.92) BGA.M15
  L3_SIGNAL w0.102: 33.83,18.19 25.71,18.19 25.44,17.92 v1(25.12,17.92)
PR23C: length 8.5
  TOP w0.102: 33.83,16.23 26.84,16.23 26.75,16.32 25.92,16.32 BGA.N15
PR23D: length 7.6
  TOP w0.102: BGA.P16 26.71,15.92 26.82,16.03 33.83,16.03
PR24A: length 7.5
  TOP w0.102: 33.83,16.81 26.84,16.81 26.75,16.72 BGA.N16
PR24B: length 9.3
  TOP w0.102: 33.83,17.01 26.85,17.01 26.75,17.12 25.12,17.12 BGA.N14
PR25C: length 8.5
  TOP w0.102: BGA.P15 25.92,15.52 26.75,15.52 26.85,15.41 33.83,15.41
PR25D: length 7.5
  TOP w0.102: BGA.R16 26.75,15.12 26.84,15.21 33.83,15.21
PT9A: length 11.4
  TOP w0.102: v1(16.32,25.12) BGA.C4
  L3_SIGNAL w0.102: 17.02,35.37 17.02,25.3 16.84,25.12 v1(16.32,25.12)
PT9B: length 11.4
  TOP w0.102: v1(17.92,25.12) BGA.B5
  L3_SIGNAL w0.102: v1(17.92,25.12) 17.4,25.12 17.22,25.29 17.22,35.37
PT9C: length 10
  TOP w0.102: BGA.B3 15.52,25.92 15.52,35.36
PT10A: length 9.1
  TOP w0.102: 16.92,35.36 16.92,26.9 16.72,26.7 BGA.A4
PT10B: length 10.8
  TOP w0.102: 17.12,35.36 17.12,25.12 BGA.C5
PT11A: length 9.1
  TOP w0.102: BGA.A5 17.52,26.75 17.61,26.84 17.61,35.36
PT11B: length 10.1
  TOP w0.102: BGA.B6 17.92,25.92 17.92,26.75 17.81,26.85 17.81,35.36
PT12A: length 9
  TOP w0.102: BGA.A3 15.92,35.36
PT12B: length 10.1
  TOP w0.102: 16.12,35.36 16.12,26.94 16.32,26.75 16.32,25.92 BGA.B4
PT14A: length 11.9
  TOP w0.102: v1(17.92,24.32) BGA.D6
  L4_SIGNAL w0.102: v1(17.92,24.32) 18.52,24.92 18.52,35.36
PT14B: length 12.7
  TOP w0.102: v1(18.72,23.52) BGA.E7
  L4_SIGNAL w0.102: v1(18.72,23.52) 19.12,23.92 19.12,24.7 18.73,25.1 18.73,35.36
PT14C: length 10.8
  TOP w0.102: 18.62,35.36 18.62,26.84 18.72,26.75 18.72,25.12 BGA.C6
PT14D: length 9.1
  TOP w0.102: 18.42,35.36 18.42,26.85 18.32,26.75 BGA.A6
PT15A: length 10.9
  TOP w0.102: v1(19.52,25.12) BGA.B7
  L3_SIGNAL w0.102: 19.32,35.37 19.32,25.71 19.52,25.51 v1(19.52,25.12)
PT15B: length 11.8
  TOP w0.102: v1(19.52,24.32) BGA.C7
  L3_SIGNAL w0.102: 19.12,35.37 BGA.C7 v1(19.52,24.32)
PT16A: length 12.6
  TOP w0.102: v1(17.92,23.52) BGA.E6
  L3_SIGNAL w0.102: 18.42,35.37 18.42,24.75 18.32,24.65 18.32,23.92 v1(17.92,23.52)
PT16B: length 11.7
  TOP w0.102: v1(18.72,24.32) BGA.D7
  L3_SIGNAL w0.102: v1(18.72,24.32) 18.72,24.65 18.63,24.74 18.63,35.37
PT17A: length 13.5
  TOP w0.102: v1(19.52,22.72) BGA.F7
  BOTTOM w0.102: v1(19.52,22.72) 19.12,23.12 19.12,25.63 19.43,25.93 19.43,35.37
PT17B: length 12.7
  TOP w0.102: v1(19.52,23.52) BGA.E8
  BOTTOM w0.102: v1(19.52,23.52) 19.92,23.92 19.92,25.64 19.63,25.93 19.63,35.37
PT17C: length 9.1
  TOP w0.102: 19.22,35.35 19.22,26.84 19.12,26.75 BGA.A7
PT17D: length 10
  TOP w0.102: BGA.B8 19.52,25.92 19.52,26.75 19.42,26.85 19.42,35.35
PT18A: length 10.8
  TOP w0.102: 20.22,35.35 20.22,26.71 20.32,26.61 20.32,25.12 BGA.C8
PT18B: length 9.1
  TOP w0.102: 20.02,35.35 20.02,26.7 19.92,26.6 BGA.A8
PT21A: length 11.7
  TOP w0.102: v1(20.32,24.32) BGA.D8
  L3_SIGNAL w0.102: 20.12,35.37 20.12,24.86 20.32,24.67 v1(20.32,24.32)
PT21B: length 13.4
  TOP w0.102: v1(20.32,22.72) BGA.E9
  L3_SIGNAL w0.102: v1(20.32,22.72) 19.92,23.12 19.92,35.37
PT22A: length 14.2
  TOP w0.102: v1(20.32,21.92) BGA.F8
  L4_SIGNAL w0.102: 20.02,35.36 20.02,24.82 19.92,24.72 BGA.F8 v1(20.32,21.92)
PT22B: length 12.8
  TOP w0.102: v1(20.32,23.52) BGA.D9
  L4_SIGNAL w0.102: v1(20.32,23.52) BGA.D9 20.72,24.7 20.22,25.19 20.22,35.36
PT22C: length 9.2
  TOP w0.102: v1(20.72,26.89) BGA.A9
  L3_SIGNAL w0.102: 20.99,35.37 20.99,27.51 20.72,27.24 v1(20.72,26.89)
PT22D: length 12
  TOP w0.102: v1(21.12,24.32) BGA.C9
  L3_SIGNAL w0.102: 21.19,35.37 21.19,26.28 20.69,25.78 20.69,24.75 v1(21.12,24.32)
PT25A: length 10
  TOP w0.102: 21.22,35.35 21.22,26.7 21.12,26.6 21.12,25.92 BGA.B9
PT25B: length 9.1
  TOP w0.102: 21.42,35.35 21.42,26.69 21.52,26.6 BGA.A10
PT26A: length 13.5
  TOP w0.102: v1(21.12,22.72) BGA.F9
  L4_SIGNAL w0.102: 21.8,35.36 21.8,24.98 21.52,24.7 21.52,23.12 v1(21.12,22.72)
PT26B: length 12.7
  TOP w0.102: v1(22.72,23.52) BGA.E11
  L4_SIGNAL w0.102: 22,35.36 22,24.98 22.32,24.66 22.32,23.92 v1(22.72,23.52)
PT27A: length 12.8
  TOP w0.102: v1(21.12,23.52) BGA.D10
  BOTTOM w0.102: v1(21.12,23.52) 20.72,23.92 20.72,25.51 21.14,25.93 21.14,35.37
PT27B: length 12.7
  TOP w0.102: v1(21.92,23.52) BGA.E10
  BOTTOM w0.102: v1(21.92,23.52) 21.52,23.92 21.52,25.75 21.34,25.93 21.34,35.37
PT27C: length 11.8
  TOP w0.102: v1(21.92,24.32) BGA.C10
  L3_SIGNAL w0.102: 21.9,35.37 21.9,24.96 21.66,24.72 21.66,24.58 v1(21.92,24.32)
PT27D: length 11.7
  TOP w0.102: v1(21.12,25.12) BGA.B10
  L3_SIGNAL w0.102: v1(21.12,25.12) 21.38,24.86 21.52,24.86 21.7,25.04 21.7,35.37
PT28A: length 9.1
  TOP w0.102: 22.22,35.35 22.22,26.84 22.32,26.75 BGA.A11
PT28B: length 10.8
  TOP w0.102: BGA.C11 21.92,25.12 21.92,26.75 22.02,26.85 22.02,35.35
PT32A: length 13.5
  TOP w0.102: v1(21.92,22.72) BGA.F10
  BOTTOM w0.102: 22.64,35.37 22.64,25.92 22.32,25.6 22.32,23.12 v1(21.92,22.72)
PT32B: length 11.9
  TOP w0.102: v1(22.72,24.32) BGA.D11
  BOTTOM w0.102: v1(22.72,24.32) 23.12,24.72 23.12,24.95 23.12,25.62 22.84,25.9 22.84,35.37
PT33A: length 10
  TOP w0.102: 22.82,35.35 22.82,26.85 22.72,26.75 22.72,25.92 BGA.B11
PT33B: length 9.1
  TOP w0.102: 23.02,35.35 23.02,26.84 23.12,26.75 BGA.A12
PT34A: length 10
  TOP w0.102: 24.42,35.35 24.42,26.85 24.32,26.75 24.32,25.92 BGA.B13
PT34B: length 9.1
  TOP w0.102: 24.62,35.35 24.62,26.84 24.72,26.75 BGA.A14
PT35A: length 11
  TOP w0.102: v1(23.52,25.12) BGA.C12
  L3_SIGNAL w0.102: v1(23.52,25.12) 23.12,25.52 23.12,35.36
PT35B: length 10.9
  TOP w0.102: v1(22.72,25.12) BGA.B12
  L3_SIGNAL w0.102: 22.92,35.36 22.92,25.32 v1(22.72,25.12)
PT36A: length 10
  TOP w0.102: BGA.B14 25.12,25.92 25.12,26.75 25.21,26.84 25.21,35.35
PT36B: length 9.1
  TOP w0.102: BGA.A15 25.52,26.75 25.41,26.85 25.41,35.35
PT36C: length 10.9
  TOP w0.102: v1(23.52,25.92) BGA.A13
  L4_SIGNAL w0.102: v1(23.52,25.92) 23.78,25.66 23.92,25.66 24.1,25.84 24.1,35.37
PT36D: length 11
  TOP w0.102: v1(24.32,25.12) BGA.C13
  L4_SIGNAL w0.102: 24.3,35.37 24.3,25.76 24.06,25.52 24.06,25.38 v1(24.32,25.12)

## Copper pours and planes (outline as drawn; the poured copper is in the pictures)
GND on L2_GND: 5.42,5.62 5.42,35.74 34.07,35.74 34.07,5.62
VCC on L5_PWR: 5.77,35.43 33.88,35.43 33.88,5.99 5.77,5.99

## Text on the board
User.Comments: RCI | RP | 08/06/14 | DWG NO: | XO3L-69E-400caBGA | REVISION | 1.0 | SHEET | 1 | OF | XO3L-69E-400CABGA PCB BREAKOUT | LATTICE SEMICONDUCTOR CORPORATION
Ref Des/Silkscreen Top: PCB BREAKOUT | XO3L-69E-400CABGA | SEMICONDUCTOR | LATTICE | A | B | C | D | E | F | G | H | J | K | L | M | N | P | R | T | 1 | 2 | 3 | 4 | 5 | 6 | 7 | 8 | 9 | 10 | 11 | 12 | 13 | 14 | 15 | 16
PAGE_OUTLINE: 1 | INITIAL RELEASE | MM/DD/YYYY | XXXX XXXXX | SPECIAL INSTRUCTIONS: | 1/2 CU OZ FOR INTERNAL AND EXTERNAL LAYERS | MIN BOARD THICKNESS IS 62MILS. | DESIGNED BY: | APPROVED BY: | SIGNATURES         DATE | REV | DESCRIPTION | ESCAPE VIA DRILL | TRACE WIDTH/SPACE | ESCAPE VIA PAD | ARRAY SIZE | BGA LAND OPENING | BGA LAND PAD | PACKAGE SIZE | PITCH | SIGNAL         (L4) | SIGNAL         (L3) | GND     PLANE  (L2) | POWER   PLANE  (L5) | PRIMARY SIDE   (L1) | SECONDARY SIDE (L6) | SECONDARY SILKSCREEN | SECONDARY SOLDERMASK | PRIMARY SOLDERMASK | PRIMARY SILKSCREEN | 0.10/0.10 | 14 x 14 | 16 x 16 | 0.3556 | 0.4572 | 0.254 | 0.8 | MM | DATE | 551.18 x 551.18 | 629.92 x 629.92 | 4/4 | 14 | 31.5 | 18 | 10 | MILS | APPROVED | PCB BREAKOUT DETAILS | 6 LAYER STACKUP | REVISION
BODY_CENTER: FIGURE | SIZE | 10.0 | ALL UNITS ARE IN MILS | SIZE MM | 0.254 | PLATED | QTY | 83 | DRILL CHART: TOP to L4_SIGNAL
PLACE_BOUND_TOP: FIGURE | SIZE | 10.0 | ALL UNITS ARE IN MILS | SIZE MM | 0.254 | PLATED | QTY | 116 | DRILL CHART: TOP to L3_SIGNAL
DISPLAY_TOP: FIGURE | SIZE | 10.0 | ALL UNITS ARE IN MILS | SIZE MM | 0.254 | PLATED | QTY | 50 | DRILL CHART: TOP to BOTTOM
